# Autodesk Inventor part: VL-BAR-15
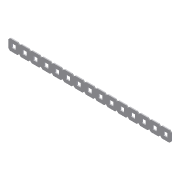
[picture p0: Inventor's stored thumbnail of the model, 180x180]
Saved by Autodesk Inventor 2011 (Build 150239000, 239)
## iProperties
Created: 2005-08
Part Number: VL-BAR-15
Document SubType Name: Sheet Metal
Density: 1 g/cm^3
Mass: 2.5361 g
Surface Area: 49.0883 cm^2
Volume: 2.5361 cm^3
Sheet Metal Rule: Default
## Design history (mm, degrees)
node "Face1"
  sketch "Sketch1"
    geometry: L1 (-15.07, 9.738)-(-23.96, 9.738); L2 (-25.865, 7.833)-(-25.865, -1.057); L3 (-23.96, -2.962)-(-15.07, -2.962); L4 (-13.165, -1.057)-(-13.165, 7.833); L5 (-25.865, 7.833)-(-23.96, 9.738); L6 (-25.865, -1.057)-(-23.96, -2.962); L7 (-15.07, -2.962)-(-13.165, -1.057); L8 (-13.165, 7.833)-(-15.07, 9.738); L9 (-21.801, 5.674)-(-17.229, 5.674); L10 (-17.229, 5.674)-(-17.229, 1.102); L11 (-17.229, 1.102)-(-21.801, 1.102); L12 (-21.801, 1.102)-(-21.801, 5.674); 4 further points
    constraints: 24 end point, 8 point on line, 4 parallel, 2 horizontal, 2 perpendicular
    dimensions: "d0" = 12.7 distance of point (-25.865, 9.738) point (-25.865, -2.962); "d1" = 12.7 distance of point (-13.165, 9.738) point (-25.865, 9.738); "d2" = 1.905 distance of L2.start point (-25.865, 9.738); "d3" = 1.905 distance of L1.end point (-25.865, 9.738) (= d2); "d4" = 1.905 distance of L2.end point (-25.865, -2.962) (= d2); "d5" = 1.905 distance of L3.start point (-25.865, -2.962) (= d4); "d6" = 1.905 distance of L3.end point (-13.165, -2.962) (= d2); "d7" = 1.905 distance of L4.start point (-13.165, -2.962) (= d6); "d8" = 1.905 distance of L4.end point (-13.165, 9.738) (= d2); "d9" = 1.905 distance of L1.start point (-13.165, 9.738) (= d8); "d10" = 4.572 distance of L11.end L9.start; "d11" = 4.572 distance of L10.end L11.end; "d12" = 4.064 distance between parallel lines of L1 L9; "d13" = 4.064 distance between parallel lines of L4 L10
pattern_linear "Rectangular Pattern1" dims "d17" = 12.7
sketch "Sketch2"
  geometry: L1 (184.531, -4.064)-(184.531, -8.636) reference; L2 (184.531, -8.636)-(179.959, -8.636) reference; L3 (179.959, -8.636)-(179.959, -4.064) reference; L4 (179.959, -4.064)-(184.531, -4.064) reference; L5 (171.831, -4.064)-(171.831, -8.636) reference; L6 (171.831, -8.636)-(167.259, -8.636) reference; L7 (167.259, -8.636)-(167.259, -4.064) reference; L8 (167.259, -4.064)-(171.831, -4.064) reference; L9 (159.131, -4.064)-(159.131, -8.636) reference; L10 (159.131, -8.636)-(154.559, -8.636) reference; L11 (154.559, -8.636)-(154.559, -4.064) reference; L12 (154.559, -4.064)-(159.131, -4.064) reference; L13 (146.431, -4.064)-(146.431, -8.636) reference; L14 (146.431, -8.636)-(141.859, -8.636) reference; L15 (141.859, -8.636)-(141.859, -4.064) reference; L16 (141.859, -4.064)-(146.431, -4.064) reference; L17 (133.731, -4.064)-(133.731, -8.636) reference; L18 (133.731, -8.636)-(129.159, -8.636) reference; L19 (129.159, -8.636)-(129.159, -4.064) reference; L20 (129.159, -4.064)-(133.731, -4.064) reference; L21 (121.031, -4.064)-(121.031, -8.636) reference; L22 (121.031, -8.636)-(116.459, -8.636) reference; L23 (116.459, -8.636)-(116.459, -4.064) reference; L24 (116.459, -4.064)-(121.031, -4.064) reference; L25 (108.331, -4.064)-(108.331, -8.636) reference; L26 (108.331, -8.636)-(103.759, -8.636) reference; L27 (103.759, -8.636)-(103.759, -4.064) reference; L28 (103.759, -4.064)-(108.331, -4.064) reference; L29 (95.631, -4.064)-(95.631, -8.636) reference; L30 (95.631, -8.636)-(91.059, -8.636) reference; L31 (91.059, -8.636)-(91.059, -4.064) reference; L32 (91.059, -4.064)-(95.631, -4.064) reference; L33 (82.931, -4.064)-(82.931, -8.636) reference; L34 (82.931, -8.636)-(78.359, -8.636) reference; L35 (78.359, -8.636)-(78.359, -4.064) reference; L36 (78.359, -4.064)-(82.931, -4.064) reference; L37 (70.231, -4.064)-(70.231, -8.636) reference; L38 (70.231, -8.636)-(65.659, -8.636) reference; L39 (65.659, -8.636)-(65.659, -4.064) reference; L40 (65.659, -4.064)-(70.231, -4.064) reference; L41 (57.531, -4.064)-(57.531, -8.636) reference; L42 (57.531, -8.636)-(52.959, -8.636) reference; L43 (52.959, -8.636)-(52.959, -4.064) reference; L44 (52.959, -4.064)-(57.531, -4.064) reference; L45 (44.831, -4.064)-(44.831, -8.636) reference; L46 (44.831, -8.636)-(40.259, -8.636) reference; L47 (40.259, -8.636)-(40.259, -4.064) reference; L48 (40.259, -4.064)-(44.831, -4.064) reference; L49 (32.131, -4.064)-(32.131, -8.636) reference; L50 (32.131, -8.636)-(27.559, -8.636) reference; L51 (27.559, -8.636)-(27.559, -4.064) reference; L52 (27.559, -4.064)-(32.131, -4.064) reference; L53 (19.431, -4.064)-(19.431, -8.636) reference; L54 (19.431, -8.636)-(14.859, -8.636) reference; L55 (14.859, -8.636)-(14.859, -4.064) reference; L56 (14.859, -4.064)-(19.431, -4.064) reference; L57 (6.731, -4.064)-(6.731, -8.636) reference; L58 (6.731, -8.636)-(2.159, -8.636) reference; L59 (2.159, -8.636)-(2.159, -4.064) reference; L60 (2.159, -4.064)-(6.731, -4.064) reference; L61 (0, 0)-(8.89, 0) reference; L62 (-1.905, -1.905)-(0, 0) reference; L63 (-1.905, -10.795)-(-1.905, -1.905) reference; L64 (0, -12.7)-(-1.905, -10.795) reference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; C1 r 2.286 at (4.445, -6.35); C2 r 2.286 at (182.245, -6.35)
  constraints: 8 tangent, 2 centre point
body "Solid1"
face "Plate1" dims "Thickness" = 1.27
other parameters: "BendRadius" = 1.27 (= Thickness), "BendReliefWidth" = 1.27 (= Thickness), "BendReliefDepth" = 0.635 (= 0.5 x Thickness), "CornerReliefSize" = 5.08 (= 4 x Thickness), "SeamGap" = 0.00508, "MinimumRemnant" = 2.54 (= 2 x Thickness), "TransitionRadius" = 1.27 (= BendRadius), "d14" = 1.27 (= BendRadius), "JacobiRadiusSize" = 1.27 (= Thickness), "GapSize" = 1.27 (= Thickness)
